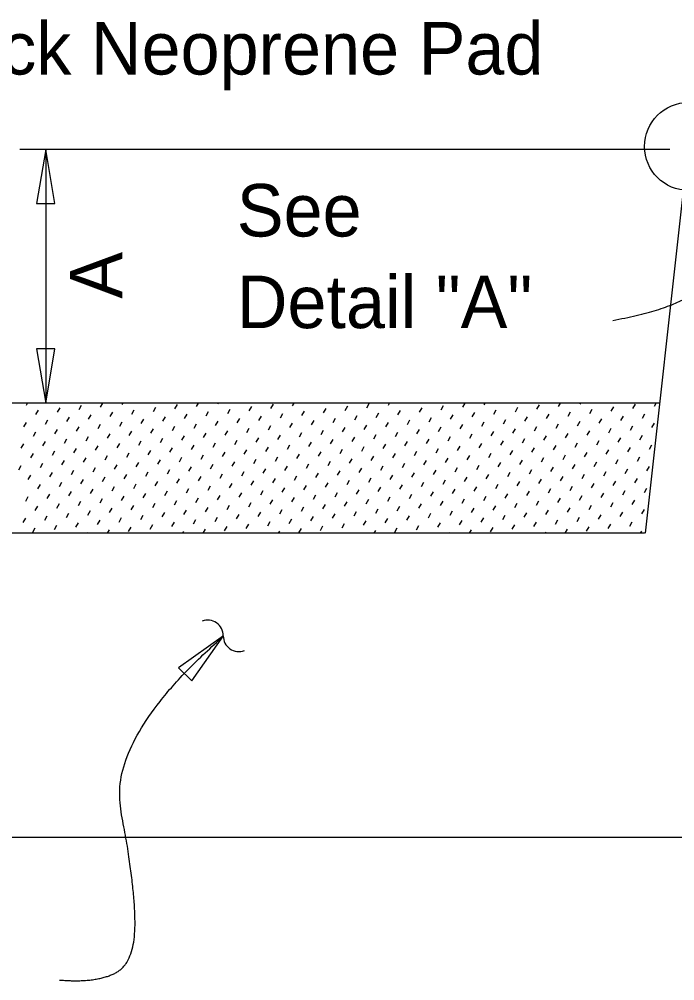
# Model space of a CAD drawing. Extents: x 21516.9 to 21586.2, y 56154.7 to 56195.
# Drawn here: x 21522.56 to 21525.078, y 56180.846 to 56184.539 of the extents above; entities that cross this region are included whole.
import ezdxf

# ---------------------------------------------------------------- set-up
doc = ezdxf.new("R2010")
doc.units = 0
for name, color, linetype in [('AdhocPoint_dp', 7, 'Continuous'), ('Border', 7, 'Continuous'), ('PlotBorder_dp', 7, 'Continuous'), ('SheetBorder_dp', 7, 'Continuous')]:
    doc.layers.add(name, color=color, linetype=linetype)

msp = doc.modelspace()

# ---------------------------------------------------------------- linework, layer by layer
at = {"layer": 'AdhocPoint_dp'}
for p, q in [((21525.1123, 56183.8906), (21524.9649, 56182.5642)), ((21524.9618, 56182.5642), (21521.0284, 56182.5642)), ((21521.0284, 56181.3976), (21526.3371, 56181.3976))]:
    msp.add_line(p, q, dxfattribs=at)
at = {"layer": 'Border'}
for p, q in [((21525.0205, 56183.0642), (21521.0284, 56183.0642)), ((21522.5876, 56183.0566), (21522.592, 56183.0642)), ((21522.6242, 56183.02), (21522.6339, 56183.0368)), ((21522.7071, 56183.0297), (21522.7169, 56183.0465)), ((21522.7901, 56183.0395), (21522.7998, 56183.0563)), ((21522.873, 56183.0492), (21522.8817, 56183.0642)), ((21522.9559, 56183.0589), (21522.959, 56183.0642)), ((21522.9926, 56183.0223), (21523.0023, 56183.0391)), ((21523.0755, 56183.032), (21523.0852, 56183.0488)), ((21523.1584, 56183.0418), (21523.1682, 56183.0585)), ((21523.2414, 56183.0515), (21523.2488, 56183.0642)), ((21523.3243, 56183.0612), (21523.3261, 56183.0642)), ((21523.3609, 56183.0246), (21523.3706, 56183.0414)), ((21523.4439, 56183.0343), (21523.4536, 56183.0511)), ((21523.5268, 56183.044), (21523.5365, 56183.0608)), ((21523.6097, 56183.0538), (21523.6158, 56183.0642)), ((21523.6463, 56183.0171), (21523.6561, 56183.0339)), ((21523.6927, 56183.0635), (21523.6931, 56183.0642)), ((21523.7293, 56183.0269), (21523.739, 56183.0437)), ((21523.8122, 56183.0366), (21523.8219, 56183.0534)), ((21523.8951, 56183.0463), (21523.9049, 56183.0631)), ((21523.9781, 56183.056), (21523.9828, 56183.0642)), ((21524.0147, 56183.0194), (21524.0244, 56183.0362)), ((21524.0976, 56183.0292), (21524.1074, 56183.0459)), ((21524.1806, 56183.0389), (21524.1903, 56183.0557)), ((21524.2635, 56183.0486), (21524.2726, 56183.0642)), ((21524.3464, 56183.0583), (21524.3499, 56183.0642)), ((21524.3831, 56183.0217), (21524.3928, 56183.0385)), ((21524.466, 56183.0314), (21524.4757, 56183.0482)), ((21524.5489, 56183.0412), (21524.5587, 56183.058)), ((21524.6319, 56183.0509), (21524.6396, 56183.0642)), ((21524.7148, 56183.0606), (21524.7169, 56183.0642)), ((21524.7514, 56183.024), (21524.7611, 56183.0408)), ((21524.8343, 56183.0337), (21524.8441, 56183.0505)), ((21524.9173, 56183.0434), (21524.927, 56183.0602)), ((21525.0002, 56183.0532), (21525.0066, 56183.0642)), ((21522.6608, 56182.9834), (21522.6705, 56183.0002)), ((21522.7437, 56182.9931), (21522.7535, 56183.0099)), ((21522.8267, 56183.0029), (21522.8364, 56183.0197)), ((21522.9096, 56183.0126), (21522.9193, 56183.0294)), ((21523.0292, 56182.9857), (21523.0389, 56183.0025)), ((21523.1121, 56182.9954), (21523.1218, 56183.0122)), ((21523.195, 56183.0051), (21523.2048, 56183.0219)), ((21523.278, 56183.0149), (21523.2877, 56183.0317)), ((21523.3975, 56182.988), (21523.4072, 56183.0048)), ((21523.4805, 56182.9977), (21523.4902, 56183.0145)), ((21523.5634, 56183.0074), (21523.5731, 56183.0242)), ((21523.6829, 56182.9805), (21523.6927, 56182.9973)), ((21523.7659, 56182.9903), (21523.7756, 56183.0071)), ((21523.8488, 56183), (21523.8585, 56183.0168)), ((21523.9318, 56183.0097), (21523.9415, 56183.0265)), ((21524.0513, 56182.9828), (21524.061, 56182.9996)), ((21524.1342, 56182.9925), (21524.144, 56183.0093)), ((21524.2172, 56183.0023), (21524.2269, 56183.0191)), ((21524.3001, 56183.012), (21524.3098, 56183.0288)), ((21524.4197, 56182.9851), (21524.4294, 56183.0019)), ((21524.5026, 56182.9948), (21524.5123, 56183.0116)), ((21524.5855, 56183.0046), (21524.5953, 56183.0213)), ((21524.6685, 56183.0143), (21524.6782, 56183.0311)), ((21524.788, 56182.9874), (21524.7977, 56183.0042)), ((21524.871, 56182.9971), (21524.8807, 56183.0139)), ((21524.9539, 56183.0068), (21524.9636, 56183.0236)), ((21522.5779, 56182.9737), (21522.5876, 56182.9905)), ((21522.6974, 56182.9468), (21522.7071, 56182.9636)), ((21522.7804, 56182.9565), (21522.7901, 56182.9733)), ((21522.8633, 56182.9663), (21522.873, 56182.983)), ((21522.9462, 56182.976), (21522.9559, 56182.9928)), ((21523.0658, 56182.9491), (21523.0755, 56182.9659)), ((21523.1487, 56182.9588), (21523.1584, 56182.9756)), ((21523.2316, 56182.9685), (21523.2414, 56182.9853)), ((21523.3146, 56182.9783), (21523.3243, 56182.9951)), ((21523.4341, 56182.9514), (21523.4439, 56182.9682)), ((21523.5171, 56182.9611), (21523.5268, 56182.9779)), ((21523.6, 56182.9708), (21523.6097, 56182.9876)), ((21523.7196, 56182.9439), (21523.7293, 56182.9607)), ((21523.8025, 56182.9537), (21523.8122, 56182.9705)), ((21523.8854, 56182.9634), (21523.8951, 56182.9802)), ((21523.9684, 56182.9731), (21523.9781, 56182.9899)), ((21524.0879, 56182.9462), (21524.0976, 56182.963)), ((21524.1708, 56182.9559), (21524.1806, 56182.9727)), ((21524.2538, 56182.9657), (21524.2635, 56182.9825)), ((21524.3367, 56182.9754), (21524.3464, 56182.9922)), ((21524.4563, 56182.9485), (21524.466, 56182.9653)), ((21524.5392, 56182.9582), (21524.5489, 56182.975)), ((21524.6221, 56182.9679), (21524.6319, 56182.9847)), ((21524.7051, 56182.9777), (21524.7148, 56182.9945)), ((21524.8246, 56182.9508), (21524.8343, 56182.9676)), ((21524.9076, 56182.9605), (21524.9173, 56182.9773)), ((21524.9905, 56182.9702), (21525.0002, 56182.987)), ((21522.6145, 56182.9371), (21522.6242, 56182.9539)), ((21522.734, 56182.9102), (21522.7437, 56182.927)), ((21522.817, 56182.9199), (21522.8267, 56182.9367)), ((21522.8999, 56182.9296), (21522.9096, 56182.9464)), ((21522.9828, 56182.9394), (21522.9926, 56182.9562)), ((21523.1024, 56182.9125), (21523.1121, 56182.9293)), ((21523.1853, 56182.9222), (21523.195, 56182.939)), ((21523.2683, 56182.9319), (21523.278, 56182.9487)), ((21523.3512, 56182.9417), (21523.3609, 56182.9584)), ((21523.4707, 56182.9148), (21523.4805, 56182.9316)), ((21523.5537, 56182.9245), (21523.5634, 56182.9413)), ((21523.6366, 56182.9342), (21523.6463, 56182.951)), ((21523.7562, 56182.9073), (21523.7659, 56182.9241)), ((21523.8391, 56182.9171), (21523.8488, 56182.9338)), ((21523.922, 56182.9268), (21523.9318, 56182.9436)), ((21524.005, 56182.9365), (21524.0147, 56182.9533)), ((21524.1245, 56182.9096), (21524.1342, 56182.9264)), ((21524.2075, 56182.9193), (21524.2172, 56182.9361)), ((21524.2904, 56182.9291), (21524.3001, 56182.9459)), ((21524.3733, 56182.9388), (21524.3831, 56182.9556)), ((21524.4929, 56182.9119), (21524.5026, 56182.9287)), ((21524.5758, 56182.9216), (21524.5855, 56182.9384)), ((21524.6588, 56182.9313), (21524.6685, 56182.9481)), ((21524.7417, 56182.9411), (21524.7514, 56182.9579)), ((21524.8612, 56182.9142), (21524.871, 56182.931)), ((21524.9442, 56182.9239), (21524.9539, 56182.9407)), ((21522.5681, 56182.8908), (21522.5779, 56182.9075)), ((21522.6511, 56182.9005), (21522.6608, 56182.9173)), ((21522.7706, 56182.8736), (21522.7804, 56182.8904)), ((21522.8536, 56182.8833), (21522.8633, 56182.9001)), ((21522.9365, 56182.893), (21522.9462, 56182.9098)), ((21523.0194, 56182.9028), (21523.0292, 56182.9196)), ((21523.139, 56182.8759), (21523.1487, 56182.8927)), ((21523.2219, 56182.8856), (21523.2316, 56182.9024)), ((21523.3049, 56182.8953), (21523.3146, 56182.9121)), ((21523.3878, 56182.905), (21523.3975, 56182.9218)), ((21523.5073, 56182.8782), (21523.5171, 56182.895)), ((21523.5903, 56182.8879), (21523.6, 56182.9047)), ((21523.6732, 56182.8976), (21523.6829, 56182.9144)), ((21523.7928, 56182.8707), (21523.8025, 56182.8875)), ((21523.8757, 56182.8804), (21523.8854, 56182.8972)), ((21523.9586, 56182.8902), (21523.9684, 56182.907)), ((21524.0416, 56182.8999), (21524.0513, 56182.9167)), ((21524.1611, 56182.873), (21524.1708, 56182.8898)), ((21524.2441, 56182.8827), (21524.2538, 56182.8995)), ((21524.327, 56182.8924), (21524.3367, 56182.9092)), ((21524.4099, 56182.9022), (21524.4197, 56182.919)), ((21524.5295, 56182.8753), (21524.5392, 56182.8921)), ((21524.6124, 56182.885), (21524.6221, 56182.9018)), ((21524.6954, 56182.8947), (21524.7051, 56182.9115)), ((21524.7783, 56182.9045), (21524.788, 56182.9212)), ((21524.8978, 56182.8776), (21524.9076, 56182.8944)), ((21524.9808, 56182.8873), (21524.9905, 56182.9041)), ((21522.6048, 56182.8541), (21522.6145, 56182.8709)), ((21522.6877, 56182.8639), (21522.6974, 56182.8807)), ((21522.8072, 56182.837), (21522.817, 56182.8538)), ((21522.8902, 56182.8467), (21522.8999, 56182.8635)), ((21522.9731, 56182.8564), (21522.9828, 56182.8732)), ((21523.056, 56182.8662), (21523.0658, 56182.8829)), ((21523.1756, 56182.8393), (21523.1853, 56182.8561)), ((21523.2585, 56182.849), (21523.2683, 56182.8658)), ((21523.3415, 56182.8587), (21523.3512, 56182.8755)), ((21523.4244, 56182.8684), (21523.4341, 56182.8852)), ((21523.544, 56182.8416), (21523.5537, 56182.8583)), ((21523.6269, 56182.8513), (21523.6366, 56182.8681)), ((21523.7098, 56182.861), (21523.7196, 56182.8778)), ((21523.8294, 56182.8341), (21523.8391, 56182.8509)), ((21523.9123, 56182.8438), (21523.922, 56182.8606)), ((21523.9952, 56182.8536), (21524.005, 56182.8704)), ((21524.0782, 56182.8633), (21524.0879, 56182.8801)), ((21524.1977, 56182.8364), (21524.2075, 56182.8532)), ((21524.2807, 56182.8461), (21524.2904, 56182.8629)), ((21524.3636, 56182.8558), (21524.3733, 56182.8726)), ((21524.4465, 56182.8656), (21524.4563, 56182.8824)), ((21524.5661, 56182.8387), (21524.5758, 56182.8555)), ((21524.649, 56182.8484), (21524.6588, 56182.8652)), ((21524.732, 56182.8581), (21524.7417, 56182.8749)), ((21524.8149, 56182.8678), (21524.8246, 56182.8846)), ((21524.9344, 56182.841), (21524.9442, 56182.8578)), ((21522.5584, 56182.8078), (21522.5681, 56182.8246)), ((21522.6414, 56182.8175), (21522.6511, 56182.8343)), ((21522.7243, 56182.8273), (21522.734, 56182.8441)), ((21522.8438, 56182.8004), (21522.8536, 56182.8172)), ((21522.9268, 56182.8101), (21522.9365, 56182.8269)), ((21523.0097, 56182.8198), (21523.0194, 56182.8366)), ((21523.0927, 56182.8295), (21523.1024, 56182.8463)), ((21523.2122, 56182.8027), (21523.2219, 56182.8195)), ((21523.2951, 56182.8124), (21523.3049, 56182.8292)), ((21523.3781, 56182.8221), (21523.3878, 56182.8389)), ((21523.461, 56182.8318), (21523.4707, 56182.8486)), ((21523.4976, 56182.7952), (21523.5073, 56182.812)), ((21523.5806, 56182.8049), (21523.5903, 56182.8217)), ((21523.6635, 56182.8147), (21523.6732, 56182.8315)), ((21523.7464, 56182.8244), (21523.7562, 56182.8412)), ((21523.866, 56182.7975), (21523.8757, 56182.8143)), ((21523.9489, 56182.8072), (21523.9586, 56182.824)), ((21524.0319, 56182.817), (21524.0416, 56182.8337)), ((21524.1148, 56182.8267), (21524.1245, 56182.8435)), ((21524.2343, 56182.7998), (21524.2441, 56182.8166)), ((21524.3173, 56182.8095), (21524.327, 56182.8263)), ((21524.4002, 56182.8192), (21524.4099, 56182.836)), ((21524.4832, 56182.829), (21524.4929, 56182.8458)), ((21524.6027, 56182.8021), (21524.6124, 56182.8189)), ((21524.6856, 56182.8118), (21524.6954, 56182.8286)), ((21524.7686, 56182.8215), (21524.7783, 56182.8383)), ((21524.8515, 56182.8312), (21524.8612, 56182.848)), ((21524.9711, 56182.8044), (21524.9808, 56182.8211)), ((21522.595, 56182.7712), (21522.6048, 56182.788)), ((21522.678, 56182.7809), (21522.6877, 56182.7977)), ((21522.7609, 56182.7907), (21522.7706, 56182.8074)), ((21522.8805, 56182.7638), (21522.8902, 56182.7806)), ((21522.9634, 56182.7735), (21522.9731, 56182.7903)), ((21523.0463, 56182.7832), (21523.056, 56182.8)), ((21523.1293, 56182.7929), (21523.139, 56182.8097)), ((21523.2488, 56182.7661), (21523.2585, 56182.7828)), ((21523.3317, 56182.7758), (21523.3415, 56182.7926)), ((21523.4147, 56182.7855), (21523.4244, 56182.8023)), ((21523.5342, 56182.7586), (21523.544, 56182.7754)), ((21523.6172, 56182.7683), (21523.6269, 56182.7851)), ((21523.7001, 56182.7781), (21523.7098, 56182.7949)), ((21523.783, 56182.7878), (21523.7928, 56182.8046)), ((21523.9026, 56182.7609), (21523.9123, 56182.7777)), ((21523.9855, 56182.7706), (21523.9952, 56182.7874)), ((21524.0685, 56182.7803), (21524.0782, 56182.7971)), ((21524.1514, 56182.7901), (21524.1611, 56182.8069)), ((21524.2709, 56182.7632), (21524.2807, 56182.78)), ((21524.3539, 56182.7729), (21524.3636, 56182.7897)), ((21524.4368, 56182.7826), (21524.4465, 56182.7994)), ((21524.5198, 56182.7923), (21524.5295, 56182.8091)), ((21524.6393, 56182.7655), (21524.649, 56182.7823)), ((21524.7222, 56182.7752), (21524.732, 56182.792)), ((21524.8052, 56182.7849), (21524.8149, 56182.8017)), ((21524.8881, 56182.7946), (21524.8978, 56182.8114)), ((21522.6316, 56182.7346), (21522.6414, 56182.7514)), ((21522.7146, 56182.7443), (21522.7243, 56182.7611)), ((21522.7975, 56182.754), (21522.8072, 56182.7708)), ((21522.9171, 56182.7272), (21522.9268, 56182.744)), ((21523, 56182.7369), (21523.0097, 56182.7537)), ((21523.0829, 56182.7466), (21523.0927, 56182.7634)), ((21523.1659, 56182.7563), (21523.1756, 56182.7731)), ((21523.2854, 56182.7294), (21523.2951, 56182.7462)), ((21523.3684, 56182.7392), (21523.3781, 56182.756)), ((21523.4513, 56182.7489), (21523.461, 56182.7657)), ((21523.5708, 56182.722), (21523.5806, 56182.7388)), ((21523.6538, 56182.7317), (21523.6635, 56182.7485)), ((21523.7367, 56182.7415), (21523.7464, 56182.7582)), ((21523.8196, 56182.7512), (21523.8294, 56182.768)), ((21523.9392, 56182.7243), (21523.9489, 56182.7411)), ((21524.0221, 56182.734), (21524.0319, 56182.7508)), ((21524.1051, 56182.7437), (21524.1148, 56182.7605)), ((21524.188, 56182.7535), (21524.1977, 56182.7703)), ((21524.3076, 56182.7266), (21524.3173, 56182.7434)), ((21524.3905, 56182.7363), (21524.4002, 56182.7531)), ((21524.4734, 56182.746), (21524.4832, 56182.7628)), ((21524.5564, 56182.7557), (21524.5661, 56182.7725)), ((21524.6759, 56182.7289), (21524.6856, 56182.7457)), ((21524.7588, 56182.7386), (21524.7686, 56182.7554)), ((21524.8418, 56182.7483), (21524.8515, 56182.7651)), ((21524.9247, 56182.758), (21524.9344, 56182.7748)), ((21524.9613, 56182.7214), (21524.9711, 56182.7382)), ((21522.5853, 56182.6883), (21522.595, 56182.7051)), ((21522.6682, 56182.698), (21522.678, 56182.7148)), ((21522.7512, 56182.7077), (21522.7609, 56182.7245)), ((21522.8341, 56182.7174), (21522.8438, 56182.7342)), ((21522.9537, 56182.6906), (21522.9634, 56182.7073)), ((21523.0366, 56182.7003), (21523.0463, 56182.7171)), ((21523.1195, 56182.71), (21523.1293, 56182.7268)), ((21523.2025, 56182.7197), (21523.2122, 56182.7365)), ((21523.322, 56182.6928), (21523.3317, 56182.7096)), ((21523.405, 56182.7026), (21523.4147, 56182.7194)), ((21523.4879, 56182.7123), (21523.4976, 56182.7291)), ((21523.6074, 56182.6854), (21523.6172, 56182.7022)), ((21523.6904, 56182.6951), (21523.7001, 56182.7119)), ((21523.7733, 56182.7048), (21523.783, 56182.7216)), ((21523.8563, 56182.7146), (21523.866, 56182.7314)), ((21523.9758, 56182.6877), (21523.9855, 56182.7045)), ((21524.0587, 56182.6974), (21524.0685, 56182.7142)), ((21524.1417, 56182.7071), (21524.1514, 56182.7239)), ((21524.2246, 56182.7169), (21524.2343, 56182.7336)), ((21524.3442, 56182.69), (21524.3539, 56182.7068)), ((21524.4271, 56182.6997), (21524.4368, 56182.7165)), ((21524.51, 56182.7094), (21524.5198, 56182.7262)), ((21524.593, 56182.7191), (21524.6027, 56182.7359)), ((21524.7125, 56182.6922), (21524.7222, 56182.709)), ((21524.7955, 56182.702), (21524.8052, 56182.7188)), ((21524.8784, 56182.7117), (21524.8881, 56182.7285)), ((21522.6219, 56182.6517), (21522.6316, 56182.6685)), ((21522.7049, 56182.6614), (21522.7146, 56182.6782)), ((21522.7878, 56182.6711), (21522.7975, 56182.6879)), ((21522.8707, 56182.6808), (21522.8805, 56182.6976)), ((21522.9903, 56182.6539), (21523, 56182.6707)), ((21523.0732, 56182.6637), (21523.0829, 56182.6805)), ((21523.1561, 56182.6734), (21523.1659, 56182.6902)), ((21523.2391, 56182.6831), (21523.2488, 56182.6999)), ((21523.3586, 56182.6562), (21523.3684, 56182.673)), ((21523.4416, 56182.666), (21523.4513, 56182.6827)), ((21523.5245, 56182.6757), (21523.5342, 56182.6925)), ((21523.6441, 56182.6488), (21523.6538, 56182.6656)), ((21523.727, 56182.6585), (21523.7367, 56182.6753)), ((21523.8099, 56182.6682), (21523.8196, 56182.685)), ((21523.8929, 56182.678), (21523.9026, 56182.6948)), ((21524.0124, 56182.6511), (21524.0221, 56182.6679)), ((21524.0953, 56182.6608), (21524.1051, 56182.6776)), ((21524.1783, 56182.6705), (21524.188, 56182.6873)), ((21524.2612, 56182.6802), (21524.2709, 56182.697)), ((21524.3808, 56182.6534), (21524.3905, 56182.6702)), ((21524.4637, 56182.6631), (21524.4734, 56182.6799)), ((21524.5466, 56182.6728), (21524.5564, 56182.6896)), ((21524.6296, 56182.6825), (21524.6393, 56182.6993)), ((21524.7491, 56182.6556), (21524.7588, 56182.6724)), ((21524.8321, 56182.6654), (21524.8418, 56182.6822)), ((21524.915, 56182.6751), (21524.9247, 56182.6919)), ((21522.6585, 56182.6151), (21522.6682, 56182.6319)), ((21522.7415, 56182.6248), (21522.7512, 56182.6416)), ((21522.8244, 56182.6345), (21522.8341, 56182.6513)), ((21522.9073, 56182.6442), (21522.9171, 56182.661)), ((21523.0269, 56182.6173), (21523.0366, 56182.6341)), ((21523.1098, 56182.6271), (21523.1195, 56182.6439)), ((21523.1928, 56182.6368), (21523.2025, 56182.6536)), ((21523.2757, 56182.6465), (21523.2854, 56182.6633)), ((21523.3952, 56182.6196), (21523.405, 56182.6364)), ((21523.4782, 56182.6293), (21523.4879, 56182.6461)), ((21523.5611, 56182.6391), (21523.5708, 56182.6559)), ((21523.6807, 56182.6122), (21523.6904, 56182.629)), ((21523.7636, 56182.6219), (21523.7733, 56182.6387)), ((21523.8465, 56182.6316), (21523.8563, 56182.6484)), ((21523.9295, 56182.6414), (21523.9392, 56182.6581)), ((21524.049, 56182.6145), (21524.0587, 56182.6313)), ((21524.132, 56182.6242), (21524.1417, 56182.641)), ((21524.2149, 56182.6339), (21524.2246, 56182.6507)), ((21524.2978, 56182.6436), (21524.3076, 56182.6604)), ((21524.4174, 56182.6168), (21524.4271, 56182.6335)), ((21524.5003, 56182.6265), (21524.51, 56182.6433)), ((21524.5833, 56182.6362), (21524.593, 56182.653)), ((21524.6662, 56182.6459), (21524.6759, 56182.6627)), ((21524.7857, 56182.619), (21524.7955, 56182.6358)), ((21524.8687, 56182.6288), (21524.8784, 56182.6456)), ((21524.9516, 56182.6385), (21524.9613, 56182.6553)), ((21522.5756, 56182.6053), (21522.5853, 56182.6221)), ((21522.6951, 56182.5784), (21522.7049, 56182.5952)), ((21522.7781, 56182.5882), (21522.7878, 56182.605)), ((21522.861, 56182.5979), (21522.8707, 56182.6147)), ((21522.9439, 56182.6076), (21522.9537, 56182.6244)), ((21523.0635, 56182.5807), (21523.0732, 56182.5975)), ((21523.1464, 56182.5905), (21523.1561, 56182.6072)), ((21523.2294, 56182.6002), (21523.2391, 56182.617)), ((21523.3123, 56182.6099), (21523.322, 56182.6267)), ((21523.4318, 56182.583), (21523.4416, 56182.5998)), ((21523.5148, 56182.5927), (21523.5245, 56182.6095)), ((21523.5977, 56182.6025), (21523.6074, 56182.6193)), ((21523.7173, 56182.5756), (21523.727, 56182.5924)), ((21523.8002, 56182.5853), (21523.8099, 56182.6021)), ((21523.8831, 56182.595), (21523.8929, 56182.6118)), ((21523.9661, 56182.6047), (21523.9758, 56182.6215)), ((21524.0856, 56182.5779), (21524.0953, 56182.5947)), ((21524.1686, 56182.5876), (21524.1783, 56182.6044)), ((21524.2515, 56182.5973), (21524.2612, 56182.6141)), ((21524.3344, 56182.607), (21524.3442, 56182.6238)), ((21524.454, 56182.5801), (21524.4637, 56182.5969)), ((21524.5369, 56182.5899), (21524.5466, 56182.6067)), ((21524.6199, 56182.5996), (21524.6296, 56182.6164)), ((21524.7028, 56182.6093), (21524.7125, 56182.6261)), ((21524.8223, 56182.5824), (21524.8321, 56182.5992)), ((21524.9053, 56182.5921), (21524.915, 56182.6089)), ((21522.6122, 56182.5687), (21522.6219, 56182.5855)), ((21522.822, 56182.5642), (21522.8244, 56182.5684)), ((21522.8993, 56182.5642), (21522.9073, 56182.5781)), ((21522.9805, 56182.571), (21522.9903, 56182.5878)), ((21523.189, 56182.5642), (21523.1928, 56182.5706)), ((21523.2664, 56182.5642), (21523.2757, 56182.5804)), ((21523.3489, 56182.5733), (21523.3586, 56182.5901)), ((21523.5561, 56182.5642), (21523.5611, 56182.5729)), ((21523.6343, 56182.5659), (21523.6441, 56182.5826)), ((21523.8458, 56182.5642), (21523.8465, 56182.5655)), ((21523.9231, 56182.5642), (21523.9295, 56182.5752)), ((21524.0027, 56182.5681), (21524.0124, 56182.5849)), ((21524.2128, 56182.5642), (21524.2149, 56182.5678)), ((21524.2902, 56182.5642), (21524.2978, 56182.5775)), ((21524.371, 56182.5704), (21524.3808, 56182.5872)), ((21524.5799, 56182.5642), (21524.5833, 56182.5701)), ((21524.6572, 56182.5642), (21524.6662, 56182.5798)), ((21524.7394, 56182.5727), (21524.7491, 56182.5895)), ((21524.9469, 56182.5642), (21524.9516, 56182.5723))]:
    msp.add_line(p, q, dxfattribs=at)
at = {"layer": 'PlotBorder_dp'}
for p, q in [((21525.0593, 56184.0389), (21522.5621, 56184.0389)), ((21522.6621, 56184.0389), (21522.6621, 56183.0642))]:
    msp.add_line(p, q, dxfattribs=at)
for points in [[(21522.6621, 56184.0389), (21522.6268, 56183.8306), (21522.6974, 56183.8306)], [(21522.6621, 56183.0642), (21522.6974, 56183.2725), (21522.6268, 56183.2725)], [(21523.3446, 56182.1699), (21523.1726, 56182.0473), (21523.2226, 56181.9975)]]:
    msp.add_lwpolyline(points, close=True, dxfattribs=at)
msp.add_circle((21525.1314, 56184.0501), 0.1691, dxfattribs=at)
for centre, start, end in [((21523.2844, 56182.1712), 359.2799, 111.0071), ((21523.4036, 56182.1697), 179.2799, 291.0071)]:
    msp.add_arc(centre, 0.0596, start, end, dxfattribs=at)
for points in [[(21524.8397, 56183.3821), (21525.059, 56183.421), (21525.2429, 56183.5519), (21525.2893, 56183.6398), (21525.3133, 56183.7838), (21525.3133, 56183.9057), (21525.2673, 56183.9677), (21525.2154, 56183.9677), (21525.2154, 56183.9277), (21525.3013, 56183.8737), (21525.3512, 56183.8737)], [(21522.715, 56180.8486), (21522.851, 56180.8365), (21523.005, 56180.9126), (21523.005, 56181.2188), (21522.8976, 56181.7759), (21523.3446, 56182.1699)]]:
    msp.add_open_spline(points, degree=2, dxfattribs=at)

# ---------------------------------------------------------------- texts
msp.add_text('Thick Neoprene Pad', height=0.2016, dxfattribs=at).set_placement((21522.1163, 56184.3264))
at = {"layer": 'SheetBorder_dp'}
for s, p in [('See', (21523.3958, 56183.7043)), ('Detail "A" ', (21523.3958, 56183.3523))]:
    msp.add_text(s, height=0.2016, dxfattribs=at).set_placement(p)
msp.add_text('A', height=0.2016, rotation=90, dxfattribs=at).set_placement((21522.9566, 56183.4654))

doc.saveas('drawing.dxf')
